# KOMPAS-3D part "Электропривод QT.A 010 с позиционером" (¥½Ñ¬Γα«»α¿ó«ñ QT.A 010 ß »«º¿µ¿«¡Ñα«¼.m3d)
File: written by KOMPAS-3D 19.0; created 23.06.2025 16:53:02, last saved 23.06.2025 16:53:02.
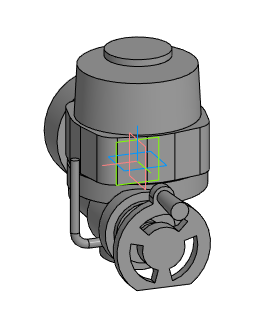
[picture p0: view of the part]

Document properties: Автор: Евгений; Полное имя файла: E:\Dendor Работа Сачек\3D для проектировщиков\3.5 Тип QT.А Электропривод\stp_Электропривод QT.A с позиционером\Электропривод QT.A 010 с позиционером.m3d

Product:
- Part/product: Электропривод QT.A 010 с позиционером

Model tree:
1. Операция без истории:1  (labels: Электропривод QT.A 010 с позиционером)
